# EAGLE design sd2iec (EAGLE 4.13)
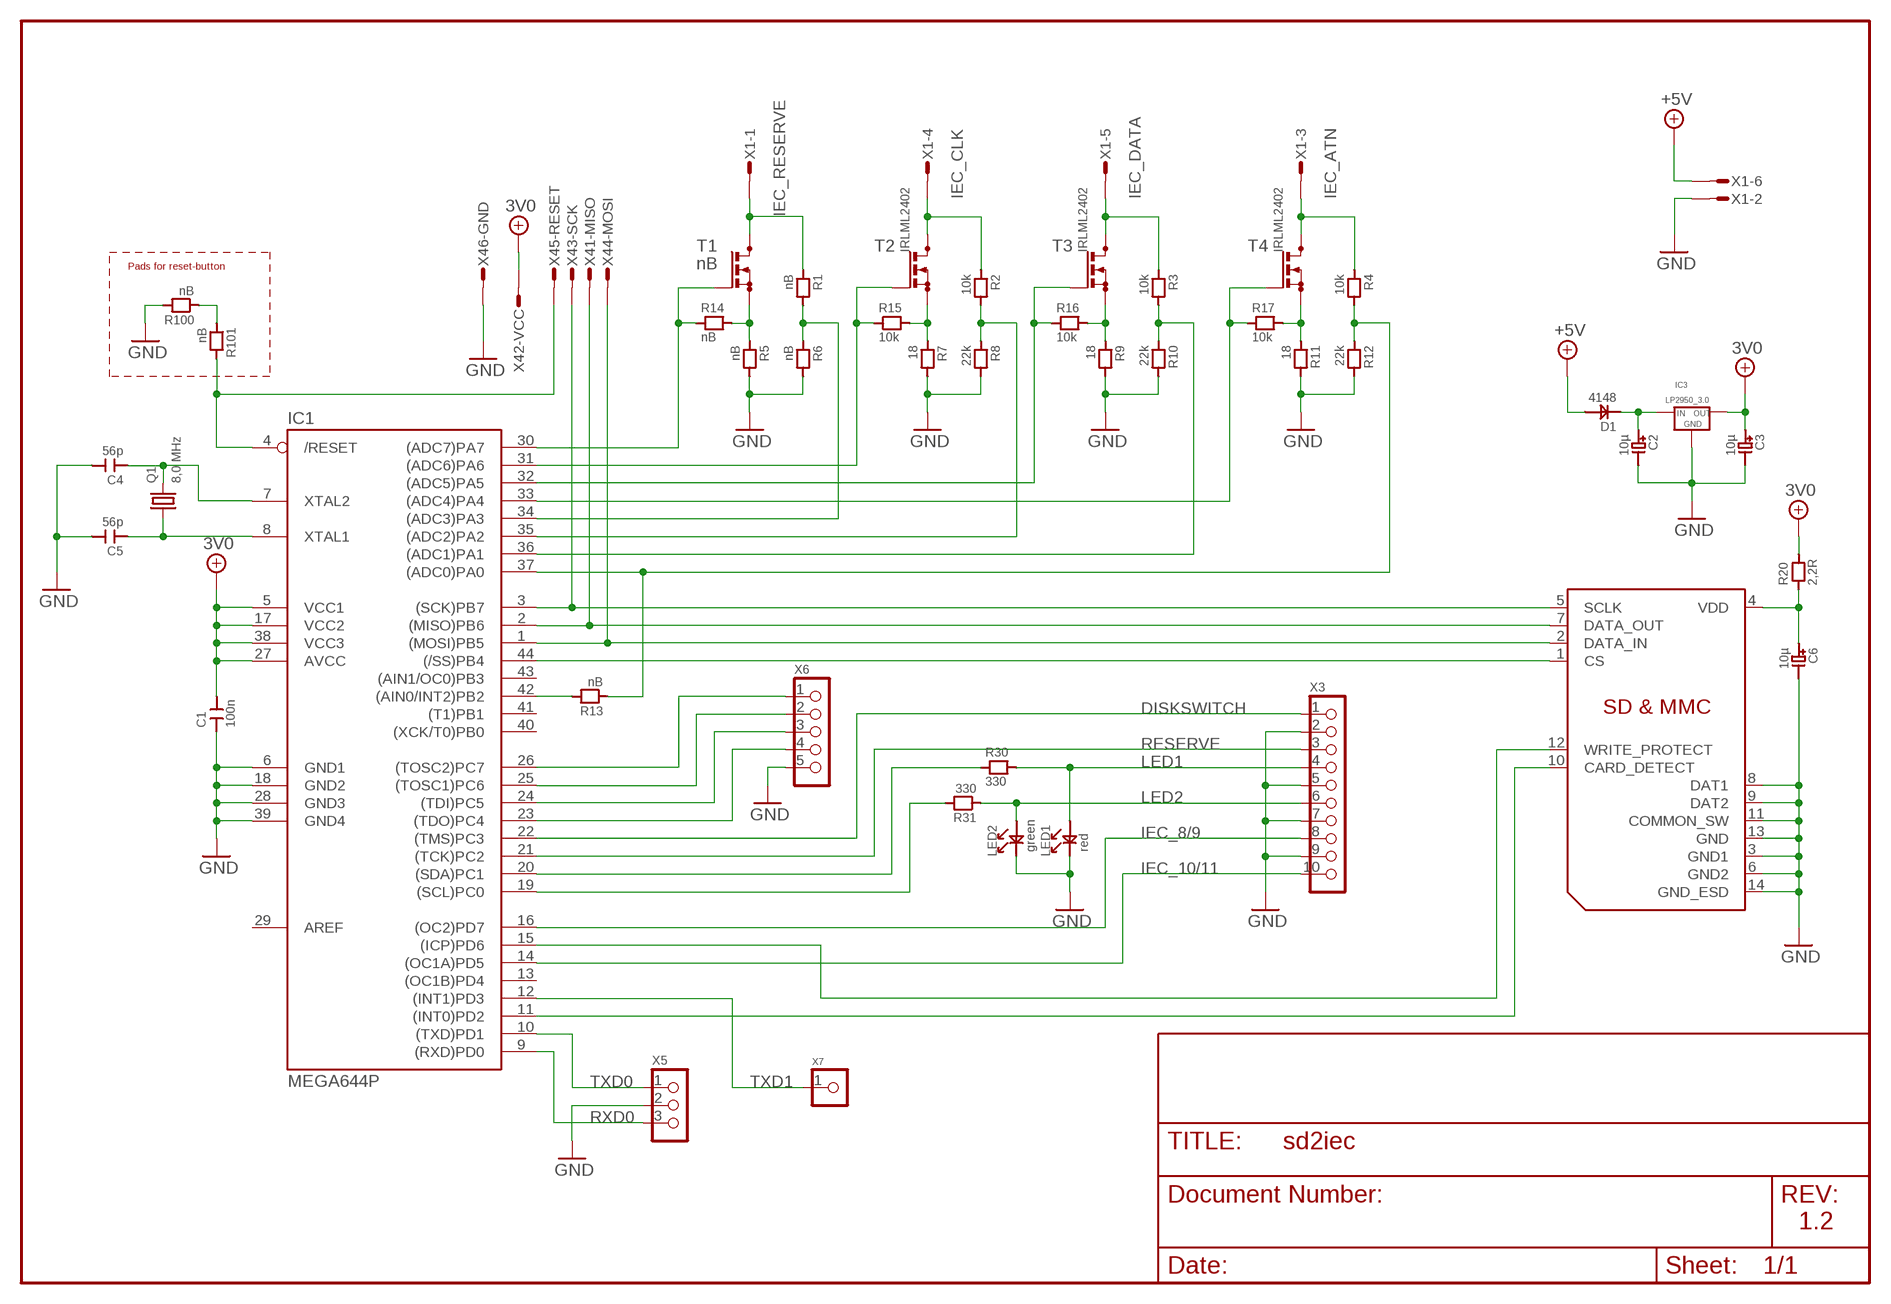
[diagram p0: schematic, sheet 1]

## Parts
C1  100n  C1206  [C1206]
C2  10µ  C_POLTA_A  [C_TANTAL_A]
C3  10µ  C_POLTA_A  [C_TANTAL_A]
C4  56p  C1206  [C1206]
C5  56p  C1206  [C1206]
C6  10µ  C_POLTA_A  [C_TANTAL_A]
D1  4148  DSOD-123  [SOD-123]
IC1  MEGA644P  MEGA16/32TQFP  [TQFP44]
IC3  LP2950_3.0  LP2950_TO92S  [TO92_S]
LED1  red  LED1206  [LED1206]
LED2  green  LED1206  [LED1206]
Q1  8,0 MHz  HC49  [HC49/S]
R1  nB  R1206  [R1206]
R2  10k  R1206  [R1206]
R3  10k  R1206  [R1206]
R4  10k  R1206  [R1206]
R5  nB  R1206  [R1206]
R6  nB  R1206  [R1206]
R7  18  R1206  [R1206]
R8  22k  R1206  [R1206]
R9  18  R1206  [R1206]
R10  22k  R1206  [R1206]
R11  18  R1206  [R1206]
R12  22k  R1206  [R1206]
R13  nB  R0603  [R0603]
R14  nB  R0805  [R0805]
R15  10k  R0805  [R0805]
R16  10k  R0805  [R0805]
R17  10k  R0805  [R0805]
R20  2,2R  R1206  [R1206]
R30  330  R1206  [R1206]
R31  330  R1206  [R1206]
R100  nB  R1206  [R1206]
R101  nB  R1206  [R1206]
T1  nB  BSN20_C  [SOT23_C]
T2  IRLML2402  BSN20_C  [SOT23_C]
T3  IRLML2402  BSN20_C  [SOT23_C]
T4  IRLML2402  BSN20_C  [SOT23_C]
X1  MICROMATCH-6_PIN  [MICROMATCH-6]
X2  SD_SCDA1A1401  [ALPS_SCDA1A1401]
X3  PINH1X10  [1X10]
X4  AVR-ISP_1X6  [1X6_ISP]
X5  PINH1X3  [1X3]
X6  PINH1X52,54  [1X5]
X7  PINH1X1  [1X1]

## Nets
3V0: C1.2 C3.1 IC1.5(VCC1) IC1.17(VCC2) IC1.27(AVCC) IC1.38(VCC3) IC3.3(OUT) R20.2 X4.2
+5V: D1.2 X1.6
/RESET: IC1.4(/RESET) R101.2 X4.5
ATN: IC1.37((ADC0)PA0) R4.2 R12.1 R13.1
CD: IC1.11((INT0)PD2) X2.10(CARD_DETECT)
CLK: IC1.35((ADC2)PA2) R2.2 R8.1
DATA: IC1.36((ADC1)PA1) R3.2 R10.1
DISKSWITCH: IC1.22((TMS)PC3) X3.1
GND: C1.1 C2.2 C3.2 C4.2 C5.2 C6.2 IC1.6(GND1) IC1.18(GND2) IC1.28(GND3) IC1.39(GND4) IC3.2(GND) LED1.1 LED2.1 R5.2 R6.2 R7.2 R8.2 R9.2 R10.2 R11.2 R12.2 R100.2 X1.2 X2.3(GND1) X2.6(GND2) X2.8(DAT1) X2.9(DAT2) X2.11(COMMON_SW) X2.13(GND) X2.14(GND_ESD) X3.2 X3.5 X3.7 X3.9 X4.6 X5.2 X6.5
IEC_8/9: IC1.16((OC2)PD7) X3.8
IEC_10/11: IC1.14((OC1A)PD5) X3.10
IEC_ATN: R4.1 T4.3(D) X1.3
IEC_CLK: R2.1 T2.3(D) X1.4
IEC_DATA: R3.1 T3.3(D) X1.5
IEC_RESERVE: R1.1 T1.3(D) X1.1
IECRESERVE: IC1.34((ADC3)PA3) R1.2 R6.1
LED1: LED1.2 R30.2 X3.4
LED2: LED2.2 R31.1 X3.6
MISO: IC1.2((MISO)PB6) X2.7(DATA_OUT) X4.1
MOSI: IC1.1((MOSI)PB5) X2.2(DATA_IN) X4.4
N$1: IC1.23((TDO)PC4) X6.4
N$2: C2.1 D1.1 IC3.1(IN)
N$3: IC1.42((AIN0/INT2)PB2) R13.2
N$4: C5.1 IC1.8(XTAL1) Q1.1
N$5: C4.1 IC1.7(XTAL2) Q1.2
N$6: C6.1 R20.1 X2.4(VDD)
N$7: IC1.24((TDI)PC5) X6.3
N$11: IC1.25((TOSC1)PC6) X6.2
N$12: IC1.26((TOSC2)PC7) X6.1
N$17: IC1.32((ADC5)PA5) R16.1 T3.1(G)
N$18: R100.1 R101.1
N$19: IC1.33((ADC4)PA4) R17.1 T4.1(G)
N$20: IC1.31((ADC6)PA6) R15.1 T2.1(G)
N$21: IC1.30((ADC7)PA7) R14.1 T1.1(G)
N$22: R5.1 R14.2 T1.2(S)
N$23: R7.1 R15.2 T2.2(S)
N$24: R9.1 R16.2 T3.2(S)
N$25: R11.1 R17.2 T4.2(S)
PC0: IC1.19((SCL)PC0) R31.2
PC1: IC1.20((SDA)PC1) R30.1
RESERVE: IC1.21((TCK)PC2) X3.3
RXD0: IC1.9((RXD)PD0) X5.3
SCK: IC1.3((SCK)PB7) X2.5(SCLK) X4.3
SS: IC1.44((/SS)PB4) X2.1(CS)
TXD0: IC1.10((TXD)PD1) X5.1
TXD1: IC1.12((INT1)PD3) X7.1
WP: IC1.15((ICP)PD6) X2.12(WRITE_PROTECT)
Unconnected: IC1.13((OC1B)PD4) IC1.29(AREF) IC1.40((XCK/T0)PB0) IC1.41((T1)PB1) IC1.43((AIN1/OC0)PB3)

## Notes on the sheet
- Pads for reset-button
- 1.2

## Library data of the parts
C1 C4 C5 = 0_rr:C
C2 C3 C6 = 0_rr:C_POL
D1 = 0_rr:D
IC1 = 0_rr:MEGA16/32: MICROCONTROLLER 16 Kbytes FLASH, 512 bytes EEPROM 1 Kbytes SRAM dual UART hardware multiplier
IC3 = 0_rr:LP2950
LED1 LED2 = 0_rr:LED
Q1 = 0_rr:HC49
R1-R17 R20 R30 R31 R100 R101 = 0_rr:R
T1-T4 = 0_rr:BSN20: N-CHANNEL MOS FET
X1 = 0_rr:MICROMATCH-6: MicroMaTch 6 7-215464-6 / 0-215464-6 Drawing Number C-215464 DDEController.pdf
X2 = 0_rr:SD
X3 = 0_rr:PINH1X10
X4 = 0_rr:AVR-ISP: MicroMaTch 6 7-215464-6 / 0-215464-6 Drawing Number C-215464 DDEController.pdf
X5 = 0_rr:PINH1X3
X6 = 0_rr:PINH1X5
X7 = 0_rr:PINH1X1

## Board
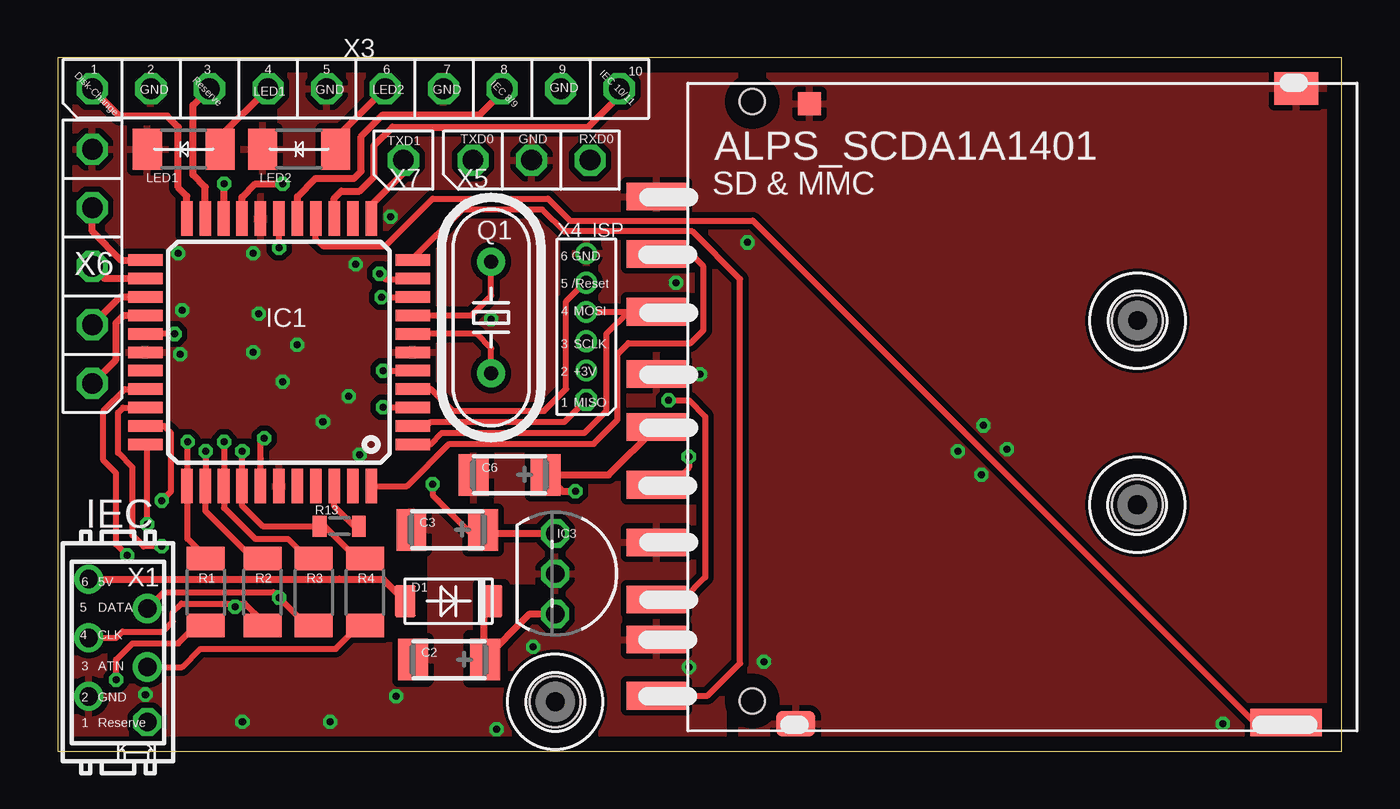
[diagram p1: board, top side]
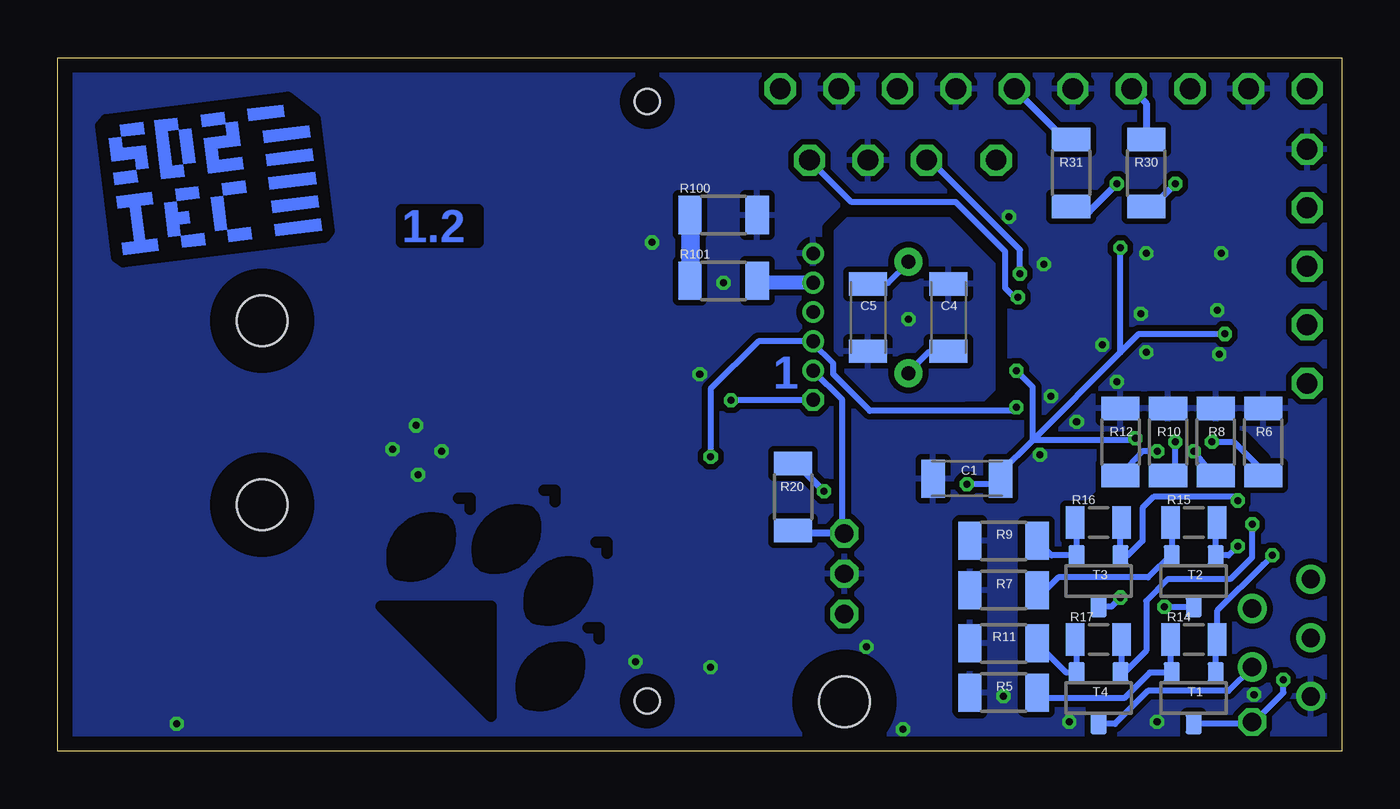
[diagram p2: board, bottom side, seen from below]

Size 55.72 x 30.08 mm. Coordinates in mm from the lower left corner, seen from the top.
Outline: 0,0 55.72,0 55.72,30.08 0,30.08 0,0
Copper layers (1*16): Top 0.035mm / dielectric 1.5mm / Bottom 0.035mm
Design rules "default": minimum track width 8mil, minimum drill 12mil, track to track 8mil, track to pad 8mil, pad to pad 8mil, via to via 8mil, smd to smd 8mil, copper to edge 25mil, drill to drill 8mil, minimum pad ring 6mil, minimum via ring 6mil, stop-mask expansion 4mil, vias tented up to drill 12mil, thermal gap 10mil
tRestrict: 30 lines
bRestrict: 22 lines

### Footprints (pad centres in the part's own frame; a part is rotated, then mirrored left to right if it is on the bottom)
C1206 = smd 1.016 x 1.651: 1 -1.462,0; 2 1.462,0
C_TANTAL_A = smd 1.3 x 1.8: 1 1.559,0; 2 -1.559,0
SOD-123 = smd 0.914 x 1.397: 1 -1.884,0; 2 1.884,0
TQFP44 = smd 1.5 x 0.5: 1 -5.8,4; 2 -5.8,3.2; 3 -5.8,2.4; 4 -5.8,1.6; 5 -5.8,0.8; 6 -5.8,0; 7 -5.8,-0.8; 8 -5.8,-1.6; 9 -5.8,-2.4; 10 -5.8,-3.2; 11 -5.8,-4; 23 5.8,-4; 24 5.8,-3.2; 25 5.8,-2.4; 26 5.8,-1.6; 27 5.8,-0.8; 28 5.8,0; 29 5.8,0.8; 30 5.8,1.6; 31 5.8,2.4; 32 5.8,3.2; 33 5.8,4 | smd 0.5 x 1.5: 12 -4,-5.8; 13 -3.2,-5.8; 14 -2.4,-5.8; 15 -1.6,-5.8; 16 -0.8,-5.8; 17 0,-5.8; 18 0.8,-5.8; 19 1.6,-5.8; 20 2.4,-5.8; 21 3.2,-5.8; 22 4,-5.8; 34 4,5.8; 35 3.2,5.8; 36 2.4,5.8; 37 1.6,5.8; 38 0.8,5.8; 39 0,5.8; 40 -0.8,5.8; 41 -1.6,5.8; 42 -2.4,5.8; 43 -3.2,5.8; 44 -4,5.8
TO92_S = drill 0.8 pad 1.219 octagon: 1 1.746,0; 2 0,0; 3 -1.746,0
LED1206 = smd 1.27 x 1.778: 1 -1.581,0; 2 1.581,0
HC49/S = drill 0.6 pad 1.219 round: 1 -2.413,0; 2 2.413,0
R1206 = smd 1.016 x 1.651: 1 -1.454,0; 2 1.454,0
R0603 = smd 0.6 x 0.9: 1 -0.85,0; 2 0.85,0
R0805 = smd 0.8 x 1.4: 1 -1.009,0; 2 1.009,0
SOT23_C = smd 0.7 x 0.9: 1 -0.953,-1.111; 2 0.953,-1.111; 3 0,1.111
2,2 = hole 2.2: 0,0
MICROMATCH-6 = drill 0.8 pad 1.118 octagon: 1 3.016,1.27 | drill 0.8 pad 1.27 round: 2 1.905,-1.27; 3 0.635,1.27; 4 -0.635,-1.27; 5 -1.905,1.27; 6 -3.175,-1.27
ALPS_SCDA1A1401 = smd 2.6 x 1.2: 1 -4.176,6.875; 2 -4.176,4.375; 3 -4.176,1.675; 4 -4.176,-0.625; 5 -4.176,-3.125; 6 -4.176,-5.625; 7 -4.176,-8.109; 8 -4.176,-9.841; 9 -4.176,9.37; 10 -4.176,-12.275 | smd 1.7 x 1.1: 11 1.865,-13.49 | smd 3.1 x 1.2: 12 23.137,-13.441 | smd 1.9 x 1.4: 13 23.576,14.062 | smd 1 x 1: 14 2.463,13.399 | hole 1.1: -0.02,13.495; -0.019,-12.505
1X10 = drill 0.9 octagon: 1 -11.43,0; 2 -8.89,0; 3 -6.35,0; 4 -3.81,0; 5 -1.27,0; 6 1.27,0; 7 3.81,0; 8 6.35,0; 9 8.89,0; 10 11.43,0
1X6_ISP = drill 0.6 pad 0.94 octagon: 1 0,0 | drill 0.6 pad 0.94 round: 2 1.27,0; 3 2.54,0; 4 3.81,0; 5 5.08,0; 6 6.35,0
1X3 = drill 0.9 octagon: 1 -2.54,0; 2 0,0; 3 2.54,0
1X5 = drill 0.9 octagon: 1 -5.08,0; 2 -2.54,0; 3 0,0; 4 2.54,0; 5 5.08,0
1X1 = drill 0.9 pad 1.27 octagon: 1 0,0

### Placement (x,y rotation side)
C1  16.27,11.83 0 bottom
C2  16.99,3.97 0 top
C3  16.91,9.6 0 top
C4  17.07,18.81 90 bottom
C5  20.56,18.81 270 bottom
C6  19.61,11.99 0 top
D1  16.96,6.51 180 top
IC1  9.6,17.3 180 top
IC3  21.59,7.7 270 top
LED1  5.48,26.11 0 top
LED2  10.48,26.11 0 top
Q1  18.81,18.81 270 top
R1  6.43,6.91 90 top
R2  8.89,6.91 90 top
R3  11.11,6.91 90 top
R4  13.34,6.91 90 top
R5  14.68,2.54 180 bottom
R6  3.41,13.41 90 bottom
R7  14.68,6.99 180 bottom
R8  5.48,13.41 90 bottom
R9  14.68,9.13 180 bottom
R10  7.54,13.41 90 bottom
R11  14.68,4.68 180 bottom
R12  9.6,13.41 90 bottom
R13  12.22,9.76 0 top
R14  6.43,4.84 180 bottom
R15  6.43,9.92 180 bottom
R16  10.56,9.92 180 bottom
R17  10.56,4.84 180 bottom
R20  23.81,11.03 270 bottom
R30  8.49,25.08 90 bottom
R31  11.75,25.08 270 bottom
R100  26.83,23.26 0 bottom
R101  26.83,20.4 0 bottom
T1  6.43,2.3 180 bottom
T2  6.43,7.38 180 bottom
T3  10.56,7.38 180 bottom
T4  10.56,2.3 180 bottom
U$1  [2,2]  46.86,18.68 0 top
U$2  [LOGO_B]  36.38,6.82 45 top
U$3  [2,2]  46.84,10.69 0 top
U$4  [2,2]  21.59,2.14 0 top
U$5  [SD2IEC_LOGO]  48.97,24.77 7 bottom
X1  2.62,4.29 270 top
X2  30.16,14.68 0 top
X3  12.94,28.73 0 top
X4  22.94,15.24 90 top
X5  20.56,25.64 0 top
X6  1.51,21.03 90 top
X7  15,25.64 0 top

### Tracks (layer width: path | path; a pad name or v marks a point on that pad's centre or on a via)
3V0  (via drill 0.3)
  Top 0.254: IC1.5 v14.13,16.51 | IC1.38 8.8,11.44 8.81,11.43 8.81,12.7 8.81,13.41 v8.97,13.57 | IC1.27 v5.07,18.1 v5.08,18.1 | 18.49,9.53 18.47,9.53 17.86,9.53 16.51,10.87 16.27,11.11 v16.27,11.59 | v9.6,21.83 IC1.17
  Top 0.305: C3.1 18.47,9.53 18.55,9.45 IC3.3
  Bottom 0.254: v5.08,18.1 8.81,18.1 9.6,17.3 | 13.41,13.49 9.6,17.3 | v14.13,16.51 13.41,15.8 13.41,13.49 | X4.2 21.67,15.24 21.67,11.27 21.67,9.53 IC3.3 | v8.97,13.57 9.13,13.49 9.45,13.49 13.41,13.49 | 9.6,17.3 v9.6,21.83 | 13.41,13.49 14.81,12.1 C1.2 14.84,11.83 | 14.84,11.83 | v16.27,11.59 15.08,11.59 14.84,11.83
  Bottom 0.305: R20.2 23.81,9.45 IC3.3
+5V
  Top 0.305: X1.6 12.22,7.46 | 12.22,7.46 13.18,7.46 | D1.2 14.13,7.46 12.22,7.46
/RESET
  Top 0.254: IC1.4 15.42,15.72 16.19,15.72 17.14,14.76 21.11,14.76 22.07,15.72 22.07,19.53 22.86,20.32 X4.5 | X4.5 | X4.5
  Bottom 0.305: 25.25,20.32 R101.2 | X4.5
  Bottom 0.61: X4.5 25.25,20.32
ATN  (via drill 0.3)
  Top 0.254: R4.2 13.02,8.33 11.59,9.76 11.27,9.76 | 11.27,9.76 8.89,9.76 8.01,10.65 IC1.37 8.02,11.51 v8.02,13.02 | 11.27,9.76 R13.1
  Bottom 0.254: R12.1 8.63,13.02 v8.02,13.02
CD
  Top 0.254: X2.10 28.21,2.41 29.61,3.81 29.61,20.48 27.54,22.54 21.99,22.54 21.03,23.5 17.54,23.5 15.4,21.36 IC1.11
CLK  (via drill 0.3)
  Top 0.254: R2.2 8.41,8.41 7.62,9.21 6.4,10.42 IC1.35 6.5,11.5 6.43,11.51 v6.43,13.02
  Bottom 0.254: R8.1 5.48,11.83 v6.43,13.02
DATA  (via drill 0.3)
  Top 0.254: v7.22,13.41 7.22,11.52 IC1.36 7.22,11.51 7.22,10.56 8.57,9.21 10,9.21 10.85,8.36 R3.2
  Bottom 0.254: R10.1 7.22,11.91 v7.22,13.41
DISKSWITCH
  Top 0.254: X3.1
  Top 0.305: IC1.22 5.6,24.08 5.24,24.45 5.24,27.07 4.76,27.54 2.7,27.54 X3.1
GND  (via drill 0.3)
  other vias: 39.05,13.02 40.08,11.99 40.16,14.13 41.2,13.1 20.64,4.52 13.1,12.86 5.24,21.59 12.94,21.11 5.32,17.22 29.92,22.07 26.83,20.32 27.86,16.35 14.45,23.18 11.51,14.29 27.38,3.65 18.81,18.73 50.56,1.19 30.64,3.89 19.05,0.95 14.68,2.38 8.02,1.27 3.81,2.46 11.83,1.27 12.62,15.4 8.73,18.97 8.49,21.59 5.4,19.13 10.4,17.62 9.76,16.03 8.49,17.3
  pour Top (isolate 0.254): 0,0 0,30.08 55.72,30.08 55.72,0
  pour Bottom (isolate 0.254): 0,0 0,30.08 55.72,30.08 55.72,0
IEC_8/9
  Top 0.305: IC1.16 10.4,24.06 11.19,24.84 12.86,24.84 13.18,25.16 13.18,26.67 14.1,27.6 18.31,27.6 19.29,28.57 X3.8 | X3.8
IEC_10/11
  Top 0.305: IC1.14 12.01,23.99 12.3,24.29 13.1,24.29 13.73,24.92 13.73,26.27 14.53,27.07 23.02,27.07 24.37,28.42 X3.10 | X3.10
IEC_ATN
  Top 0.254: X1.3 5.4,3.65 6.19,4.45 12.06,4.45 13.1,5.48 13.26,5.48 R4.1
  Bottom 0.254: T4.3 9.84,1.19 8.41,2.62 4.92,2.62 X1.3 | X1.3 | X1.3
IEC_CLK  (via drill 0.3)
  Top 0.254: X1.4 2.54,4.92 2.8,5.18 4.55,5.18 5,5.64 5,6.03 5.37,6.4 7.7,6.4 | R2.1 8.89,5.64 8.12,6.4 7.7,6.4 | 7.7,6.4 v7.7,6.27
  Bottom 0.254: v7.7,6.27 T2.3
IEC_DATA  (via drill 0.3)
  Top 0.254: X1.5 4.6,6.91 9.37,6.91 v9.6,6.67 | v9.6,6.67 | R3.1 10.82,5.45 v9.6,6.67
  Bottom 0.254: T3.3 10,6.27 v9.6,6.67
IEC_RESERVE  (via drill 0.3)
  Top 0.254: R1.1 6.04,5.48 5.24,4.68 3.25,4.68 2.54,3.97 v2.54,3.1
  Bottom 0.254: 3.81,1.27 | X1.1 3.81,1.27 | 3.81,1.27 2.54,2.54 v2.54,3.1 2.54,3.02 | X1.1 | T1.3 3.97,1.19 X1.1
IECRESERVE  (via drill 0.3)
  Top 0.254: R1.2 6.44,8.41 5.64,9.21 5.64,11.51 | 5.64,11.51 5.64,11.59 5.6,11.56 IC1.34 5.64,11.51 | 5.64,11.51 v5.64,13.41
  Bottom 0.254: R6.1 3.41,12.14 4.68,13.41 v5.64,13.41
LED1
  Top 0.305: X3.4 | LED1.2 7.06,26.66 X3.4
  Bottom 0.305: X3.4 | R30.2 8.49,28.1 X3.4
LED2
  Top 0.305: X3.6 | LED2.2 12.06,26.58 X3.6
  Bottom 0.305: X3.6 | R31.1 12.01,26.54 X3.6
MISO  (via drill 0.3)
  Top 0.254: IC1.2 15.43,14.13 16.03,14.13 16.19,14.29 21.99,14.29 X4.1 | X4.1 | X4.1 | X2.7 27.13,6.58 28.1,7.54 28.1,14.53 27.41,15.21 v26.51,15.21
  Bottom 0.254: X4.1 22.94,15.21 v26.51,15.21 | X4.1
MOSI
  Top 0.254: X4.4 | 24.77,19.05 X4.4 | 24.77,19.05 25.96,19.05 | 25.96,19.05 25.98,19.05 X2.2 25.96,19.06 25.96,19.05 | IC1.1 16.16,13.3 16.67,13.81 22.86,13.81 23.81,14.76 23.81,18.1 24.77,19.05
N$1
  Top 0.305: IC1.23 2.75,21.3 1.51,22.54 X6.4 | X6.4 | X6.4 1.51,23.65
N$2
  Top 0.305: D1.1 18.49,6.15 18.49,3.97 | C2.1 18.49,3.97 | IC3.1 20.48,5.95 18.49,3.97
N$3
  Top 0.254: R13.2 12.86,9.76 12.01,10.62 IC1.42
N$4
  Top 0.254: IC1.8 17.95,18.9 18.81,19.76 Q1.1 18.81,21.27
  Bottom 0.254: Q1.1 18.81,21.19 19.69,20.31 C5.1
N$5
  Top 0.254: IC1.7 18.17,18.1 18.81,17.46 Q1.2
  Bottom 0.254: Q1.2 18.81,16.43 17.93,17.31 C4.1
N$6  (via drill 0.3)
  Top 0.305: X2.4 23.91,11.99 C6.1 21.11,12.06 21.91,11.27 v22.46,11.27
  Bottom 0.305: R20.1 23.81,12.61 v22.46,11.27
N$7
  Top 0.305: X6.3 2.04,20.5 IC1.24
N$11
  Top 0.305: X6.2 | IC1.25 2.72,19.7 X6.2
N$12
  Top 0.305: IC1.26 2.87,18.9 2.54,18.57 2.54,16.99 X6.1 | X6.1
N$17  (via drill 0.3)
  Top 0.254: IC1.32 4.63,14.1 4.92,13.81 4.92,11.27 v4.52,10.87 | v4.52,10.87
  Bottom 0.254: v4.52,10.87 | v4.52,10.87 4.68,11.03 8.18,11.03 8.65,10.56 8.65,9.13 9.29,8.49 T3.1 | T3.1 | R16.1 9.6,9.87 T3.1
N$18
  Bottom 0.813: R101.1 28.26,20.4 28.26,23.26 R100.1
N$19  (via drill 0.3)
  Top 0.254: IC1.33 3.89,13.38 v3.89,9.84
  Bottom 0.254: v3.89,9.84 3.89,8.41 4.84,7.46 7.54,7.46 8.49,6.51 8.49,4.37 9.45,3.41 9.53,3.41 | 9.53,3.41 T4.1 | R17.1 9.55,3.44 9.53,3.41
N$20  (via drill 0.3)
  Top 0.254: IC1.31 2.84,14.9 2.62,14.68 2.62,12.94 3.25,12.3 3.25,9.37 3.73,8.89 v4.52,8.89
  Bottom 0.254: v4.52,8.89 4.92,8.49 T2.1 | T2.1 | T2.1 | R15.1 5.48,9.87 T2.1
N$21  (via drill 0.3)
  Top 0.254: IC1.30 2.92,15.7 1.98,14.76 1.98,12.62 2.54,12.06 2.54,8.97 v3.02,8.49
  Bottom 0.254: v3.02,8.49 3.41,8.1 5.4,6.11 5.4,4.84 R14.1 5.42,4.74 5.48,4.68 T1.1
N$22
  Bottom 0.254: 7.44,3.36 T1.2 8.34,3.41 9.45,2.3 13.18,2.3 13.23,2.36 R5.1 | R14.2 7.44,3.36 | 7.44,3.36 7.46,3.33
N$23
  Bottom 0.254: R7.1 12.86,6.99 12.3,7.54 8.41,7.54 7.38,8.57 7.38,8.81 T2.2 7.38,9.87 R15.2
N$24
  Bottom 0.254: R9.1 12.6,8.49 T3.2 | T3.2 | T3.2 | R16.2 11.51,9.87 T3.2
N$25
  Bottom 0.254: R11.1 11.96,3.41 T4.2 | T4.2 | T4.2 | R17.2 11.51,4.79 T4.2
PC0  (via drill 0.3)
  Top 0.305: 8.02,23.12 IC1.19 8.01,24.04 8.57,24.61 v9.76,24.61
  Bottom 0.305: R31.2 11.75,23.42 10.95,23.42 v9.76,24.61
PC1  (via drill 0.3)
  Top 0.305: IC1.20 7.22,23.12 v7.22,24.61
  Bottom 0.305: R30.1 8.41,23.42 v7.22,24.61
RESERVE
  Top 0.254: X3.3
  Top 0.305: IC1.21 6.4,24.47 5.87,25 5.87,28.02 X3.3
RXD0  (via drill 0.3)
  Top 0.254: IC1.9 15.39,19.68 v14.05,19.68
  Bottom 0.254: v14.05,19.68 14.21,19.68 14.61,20.08 14.61,21.67 16.75,23.81 21.27,23.81 X5.3
SCK  (via drill 0.3)
  Top 0.254: X2.5 26.51,11.56 26.59,11.51 27.38,12.3 v27.38,12.78 | IC1.3 15.39,14.92 v14.13,14.92
  Bottom 0.254: X4.3 | X4.3 | v14.13,14.92 14.29,14.76 20.48,14.76 22.07,16.35 22.07,16.83 22.94,17.7 X4.3 | X4.3 | v27.38,12.78 27.38,15.72 25.32,17.78 X4.3 | X4.3 | X4.3
SS
  Top 0.254: IC1.44 15.15,11.5 16.99,13.34 23.26,13.34 24.29,14.37 24.29,17.22 24.77,17.7 27.46,17.7 28.02,18.26 28.02,21.03 27.46,21.59 25.96,21.59 X2.1 | X2.1
TXD0  (via drill 0.3)
  Top 0.254: IC1.10 15.38,20.48 14.21,20.48 v13.97,20.72
  Bottom 0.254: v13.97,20.72 13.97,21.75 16.75,24.53 17.86,25.64 X5.1
TXD1
  Top 0.305: IC1.12 13.6,23.68 15,25.08 X7.1
WP
  Top 0.254: IC1.15 11.2,22.21 11.51,21.91 14.21,21.91 16.27,23.97 21.27,23.97 22.23,23.02 30.16,23.02 52.03,1.15 | 52.03,1.15 53.34,1.11 | 52.03,1.15 X2.12

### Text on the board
Bottom: 1.2 | 1
tPlace: 1 | 2 | Reserve | 3 | 4 | 5 | 6 | 7 | IEC 8/9 | 8 | GND | 9 | IEC 10/11 | 10 | Disk-Change | GND | LED1 | GND | LED2 | GND | TXD1 | TXD0 | GND | RXD0 | ISP | 6 | GND | 5 | /Reset | 4 | MOSI | 3 | SCLK | 2 | +3V | 1 | MISO | IEC | 6 | 5V | 5 | DATA | 4 | CLK | 3 | ATN | 2 | GND | 1 | Reserve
